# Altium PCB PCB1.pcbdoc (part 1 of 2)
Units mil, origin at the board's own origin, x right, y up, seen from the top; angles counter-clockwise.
Board outline 9373 x 7411 mil, 2 copper layers (Top Layer, Bottom Layer); 228 components, 128 nets, 653 pads, 371 vias.
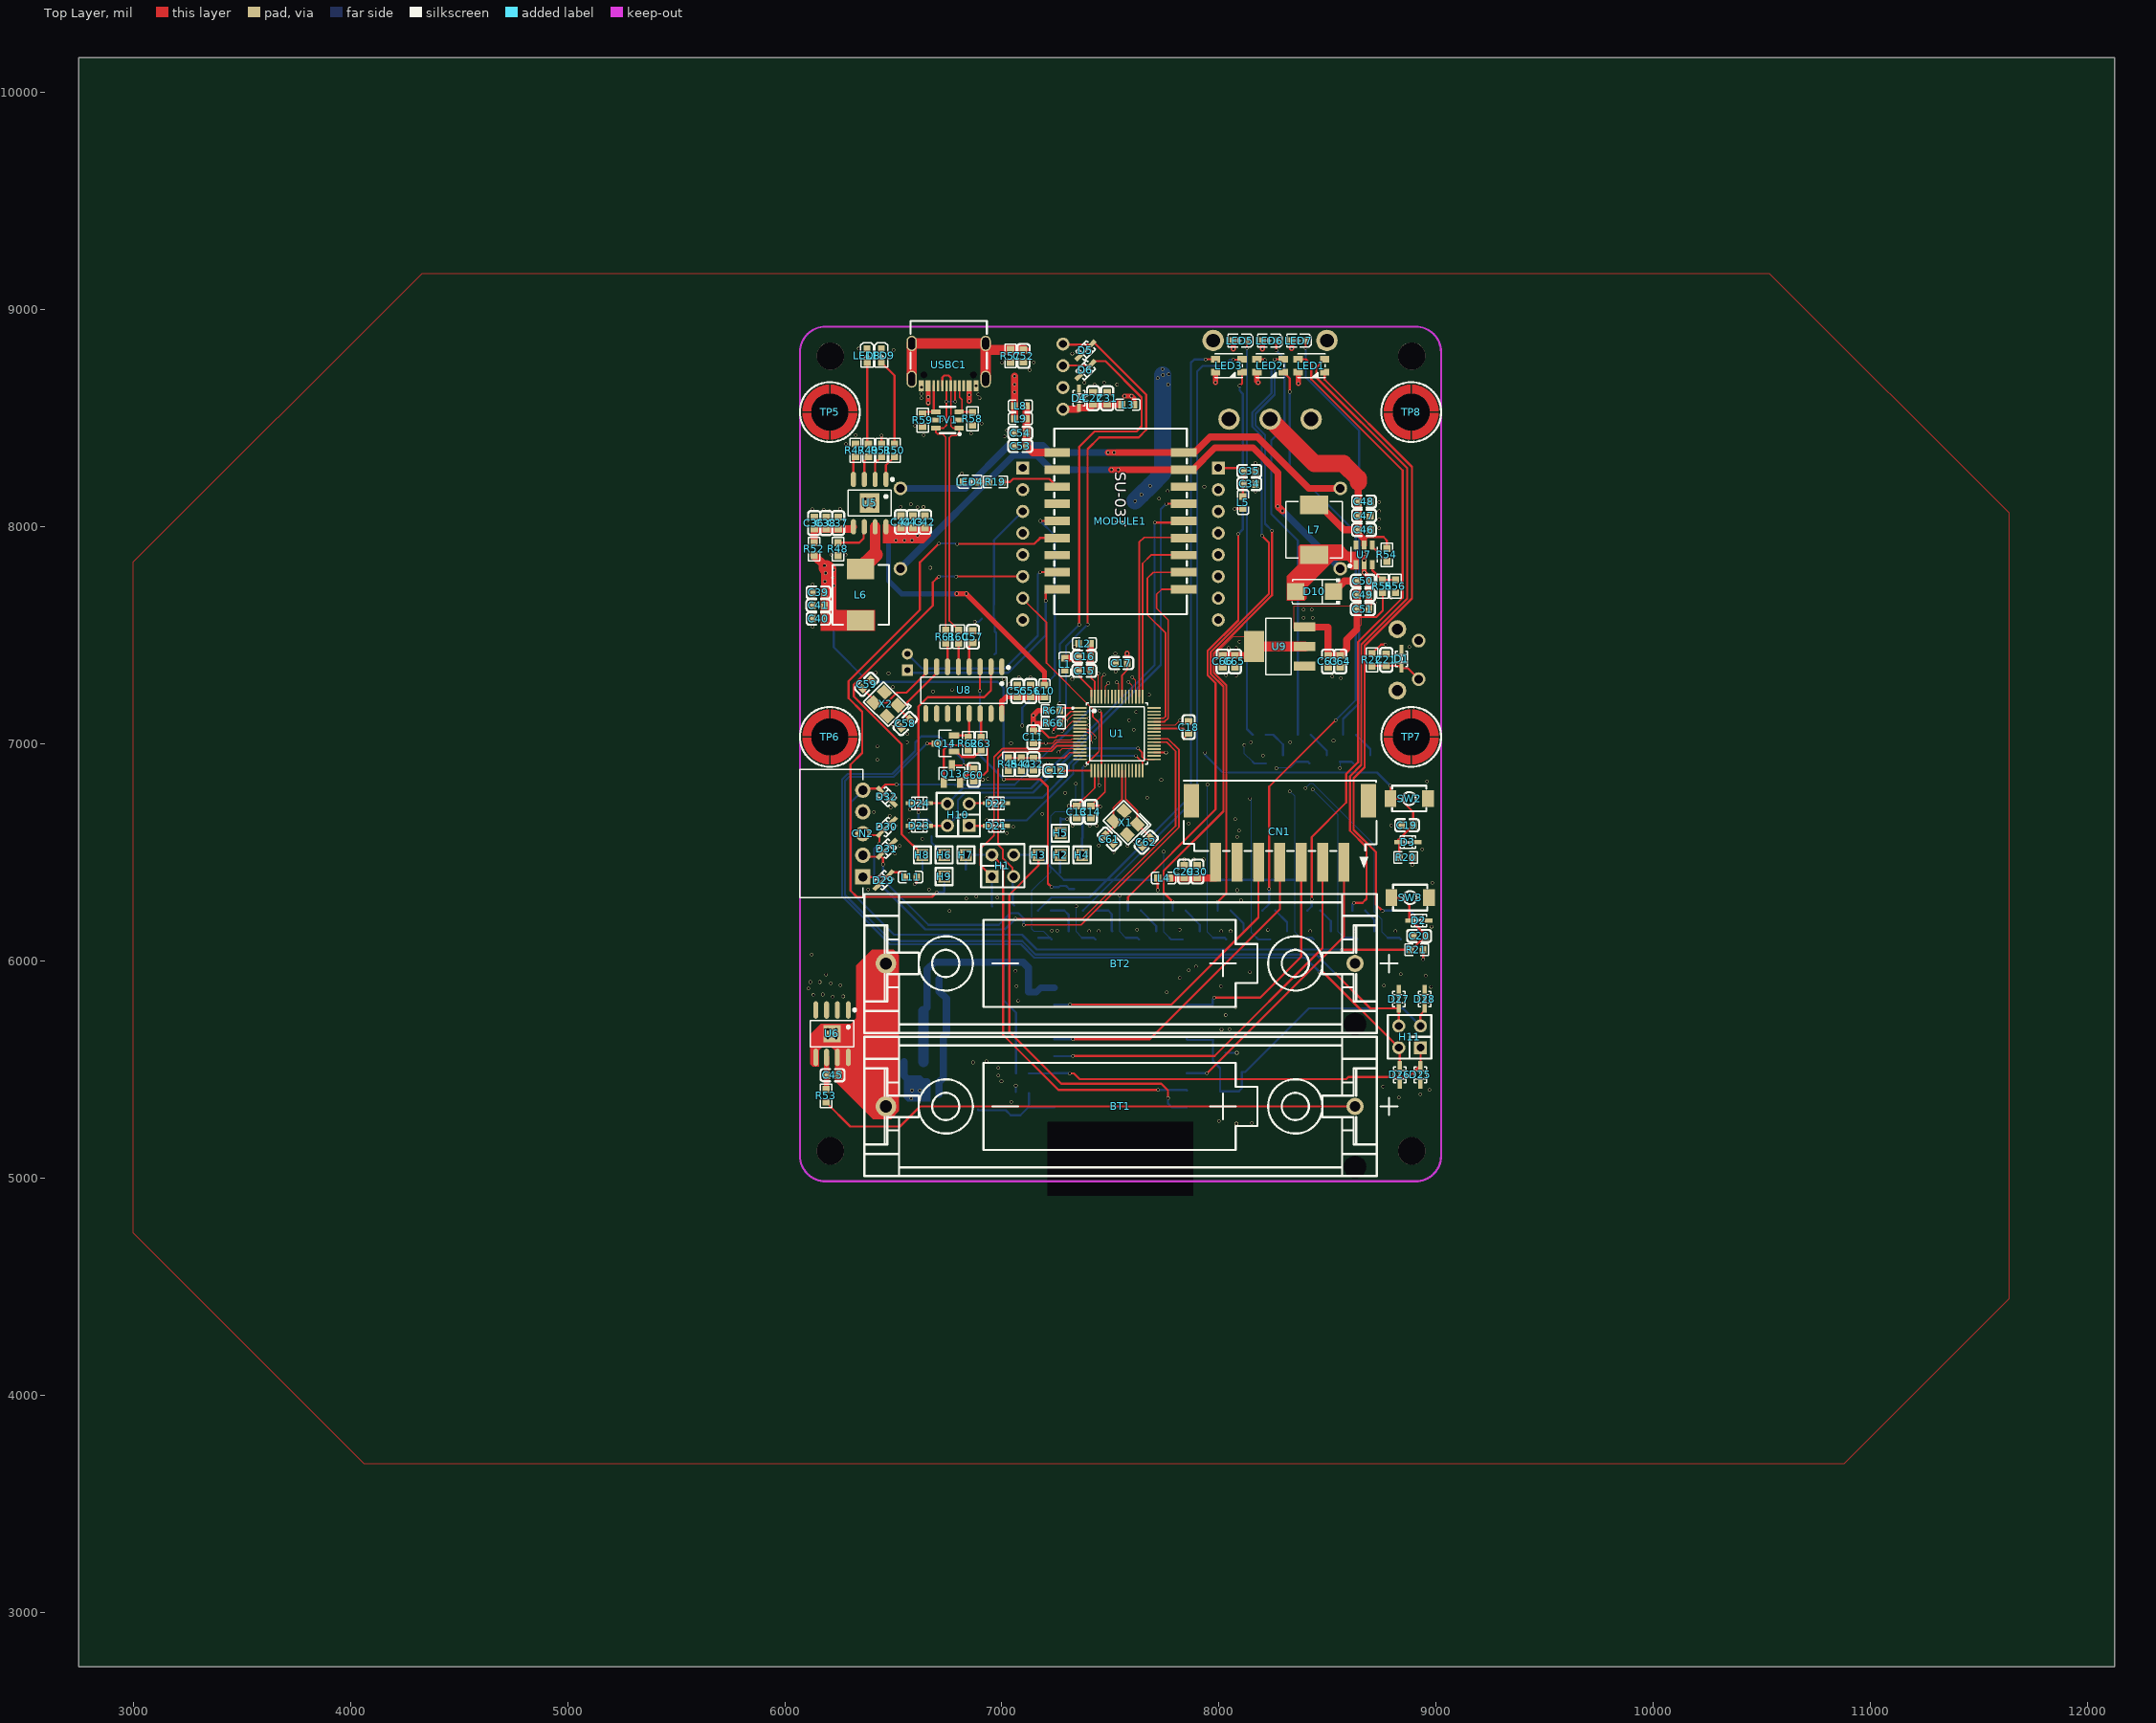
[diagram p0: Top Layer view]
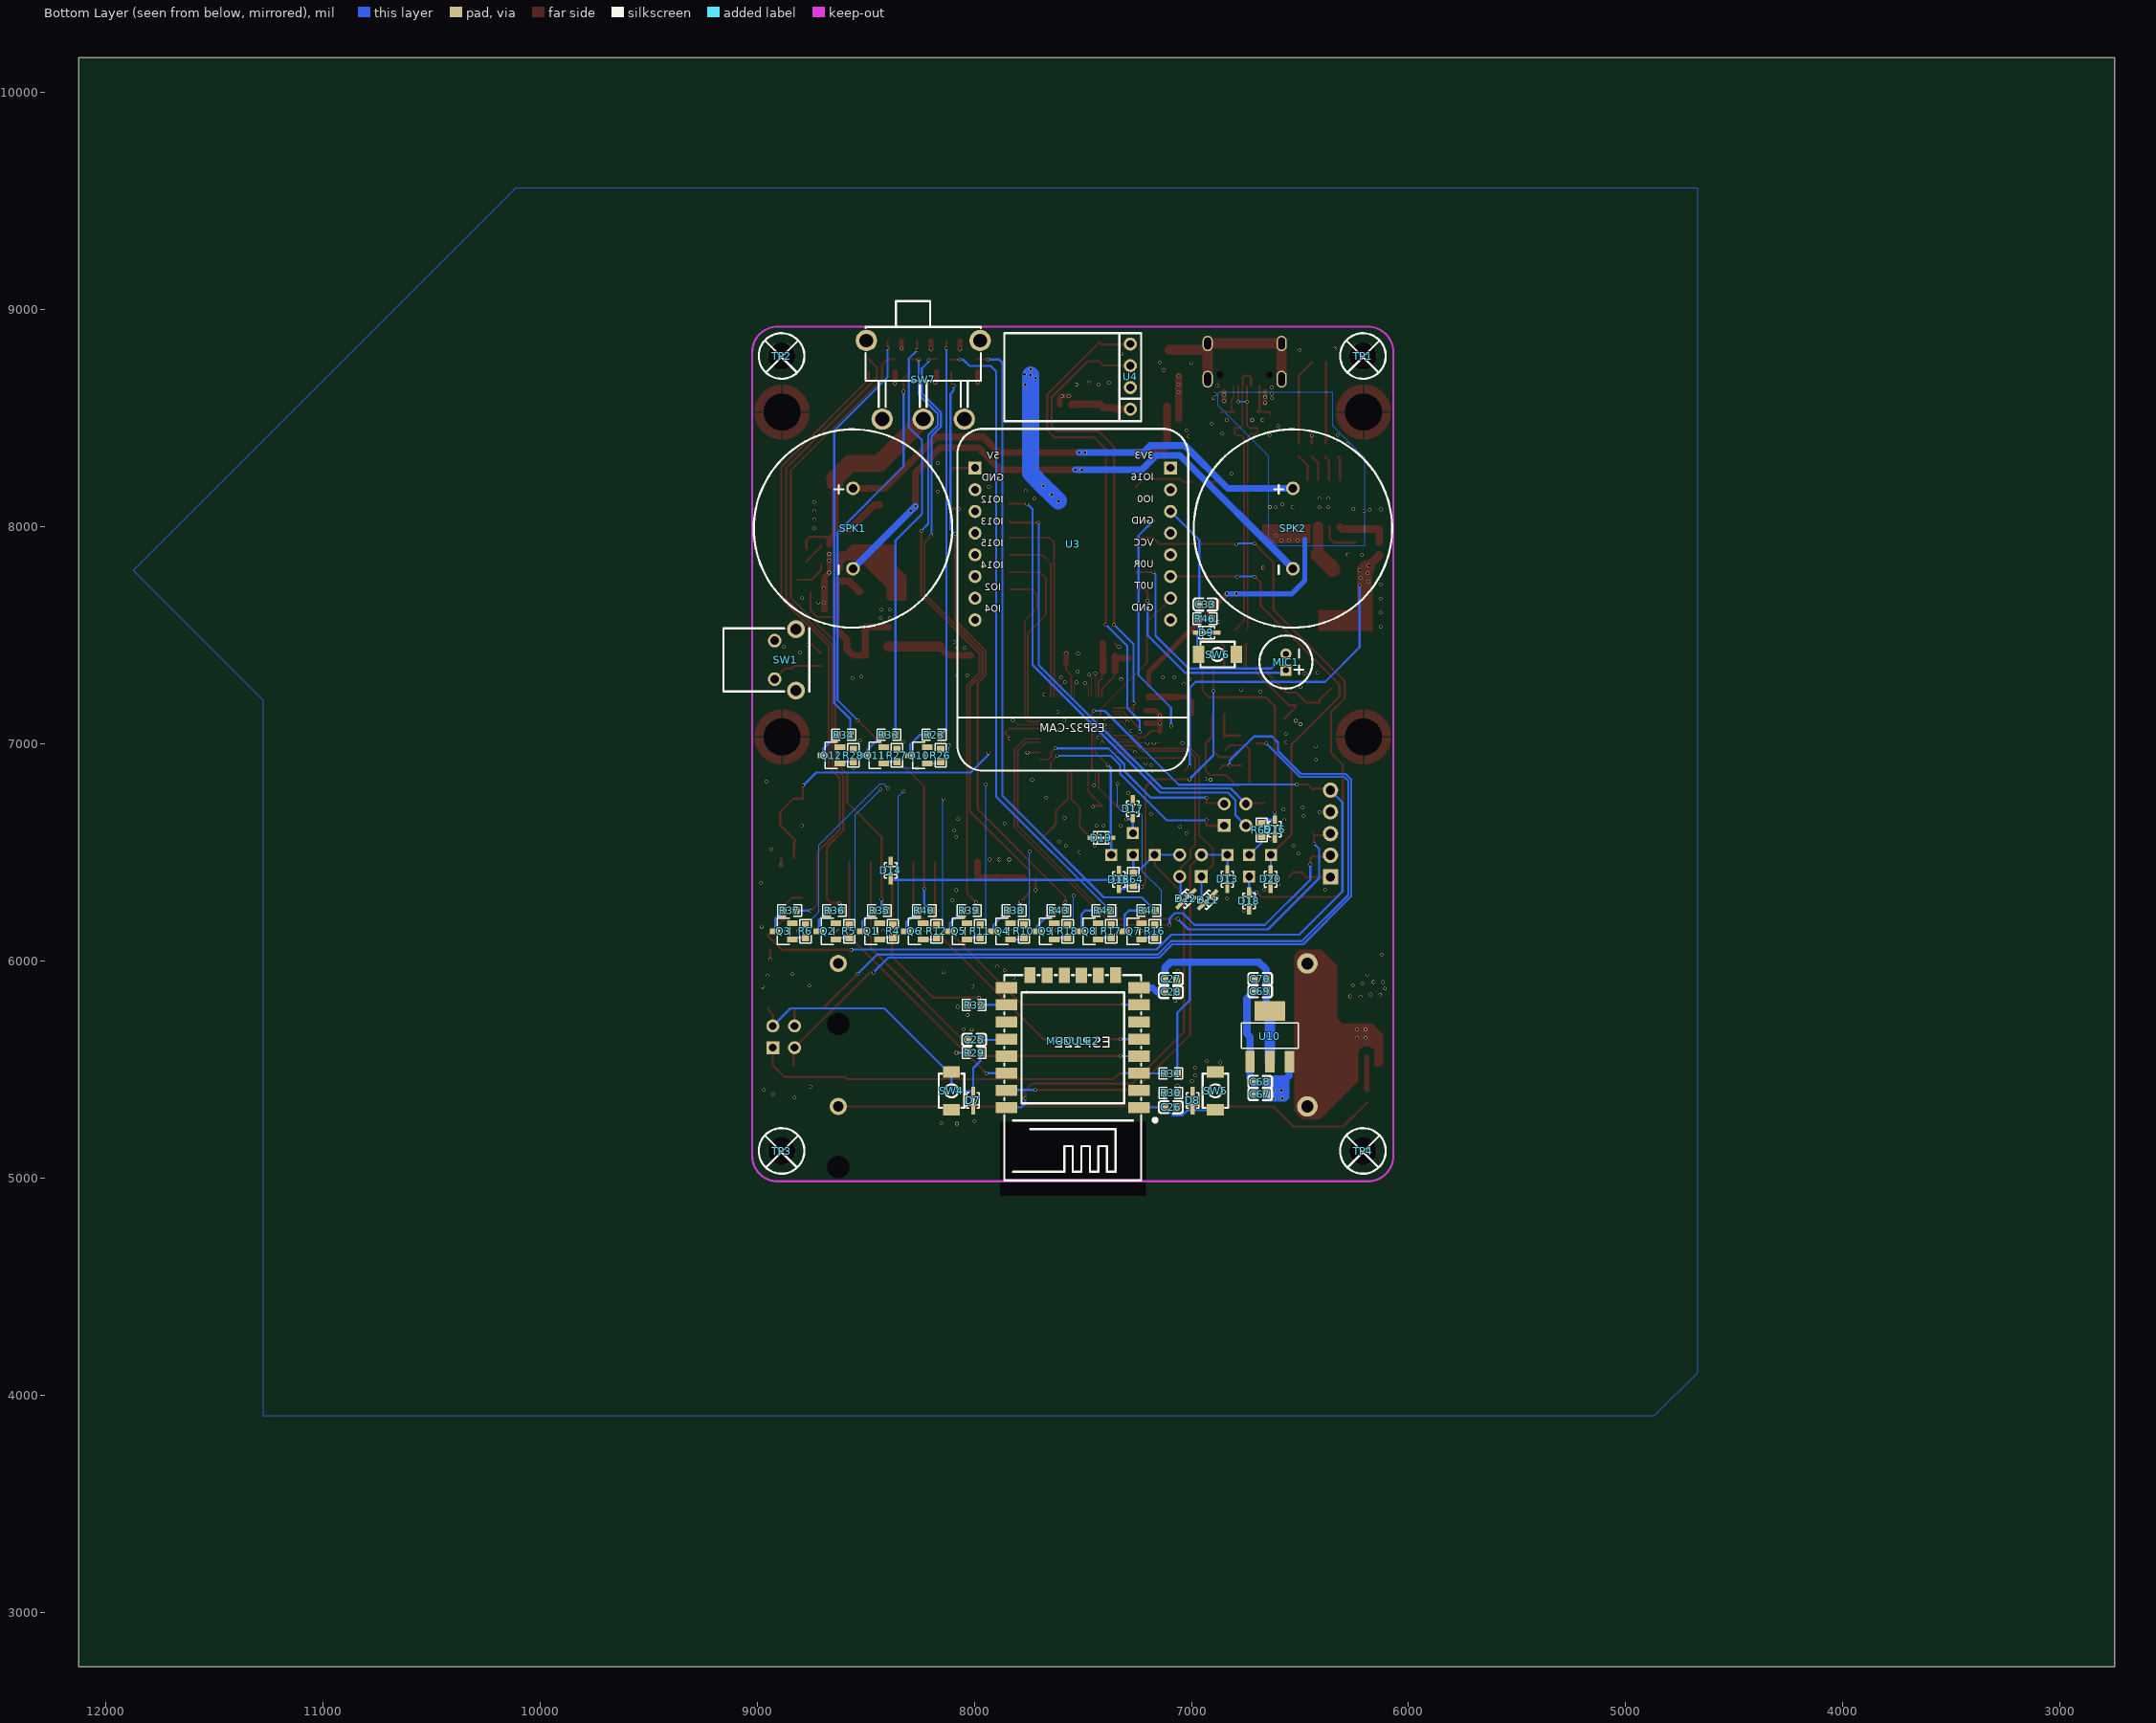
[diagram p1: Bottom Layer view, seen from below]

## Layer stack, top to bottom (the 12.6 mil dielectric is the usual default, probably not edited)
Top Layer: signal copper (thickness not stored)
Dielectric: dielectric 12.6, FR-4, Dk 4.8
Bottom Layer: signal copper (thickness not stored)

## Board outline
12123,2750 2750,2750 2750,10161 12123,10161
cut-out: 7211.73,4920.98 7881.02,4920.98 7881.02,5259.09 7211.73,5259.09

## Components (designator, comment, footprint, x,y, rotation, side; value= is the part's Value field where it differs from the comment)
BT1 "1028" BAT-TH_KEYSTONE-1028 7546.38,5331.3 r180 top
BT2 "1028" BAT-TH_KEYSTONE-1028 7546.38,5989.93 r180 top
C11 "CAP_0603" C0603 7145,7033 r90 top
C12 "CAP_0603" C0603 7245,6878 r180 top
C13 "CAP_0603" C0603 7345,6688 r90 top
C14 "CAP_0603" C0603 7410,6688 r90 top
C15 "CAP_0603" C0603 7379.59,7337.8 r180 top
C16 "CAP_0603" C0603 7380,7403 r180 top
C17 "CAP_0603" C0603 7550,7373 r0 top
C18 "CAP_0603" C0603 7860,7078 r270 top
C19 "CAP_0603" C0603 8866.25,6626.15 r0 top
C20 "CAP_0603" C0603 8922.02,6116.15 r0 top
C21 "CAP_0603" C0603 8770,7388 r270 top
C22 "CAP_0603" C0603 7420,8593 r270 top
C25 "CAP_0603" C0603 8000,5638 r180 bottom
C26 "CAP_0603" C0603 7095,5328 r0 bottom
C27 "CAP_0603" C0603 7095,5918 r0 bottom
C28 "CAP_0603" C0603 7095,5858 r0 bottom
C29 "CAP_0603" C0603 7839.59,6412.8 r270 top
C30 "CAP_0603" C0603 7899.59,6412.8 r270 top
C31 "CAP_0603" C0603 7485,8593 r90 top
C32 "CAP_0603" C0603 7145,6908 r90 top
C33 "CAP_0603" C0603 6935.47,7643 r0 bottom
C34 "CAP_0603" C0603 8140,8198 r0 top
C35 "CAP_0603" C0603 8140,8258 r0 top
C36 "CAP_0603" C0603 6136.03,8018.48 r90 top
C37 "CAP_0603" C0603 6246.03,8018.48 r90 top
C38 "CAP_0603" C0603 6191.03,8018.48 r90 top
C39 "CAP_0603" C0603 6155.69,7698.31 r180 top
C40 "CAP_0603" C0603 6155.69,7578.31 r180 top
C41 "CAP_0603" C0603 6155.49,7638.72 r180 top
C42 "CAP_0603" C0603 6646.03,8023.48 r90 top
C43 "CAP_0603" C0603 6591.03,8023.48 r90 top
C44 "CAP_0603" C0603 6536.03,8023.48 r90 top
C45 "CAP_0603" C0603 6220.46,5475.23 r0 top
C46 "CAP_0603" C0603 8668,7986.89 r0 top
C47 "CAP_0603" C0603 8668,8051.89 r0 top
C48 "CAP_0603" C0603 8668,8116.89 r0 top
C49 "CAP_0603" C0603 8663,7686.89 r0 top
C50 "CAP_0603" C0603 8663,7751.89 r0 top
C51 "CAP_0603" C0603 8663,7621.89 r0 top
C52 "CAP_0603" C0603 7100,8788 r90 top
C53 "CAP_0603" C0603 7085,8373 r0 top
C54 "CAP_0603" C0603 7085,8433 r0 top
C55 "CAP_0603" C0603 7071.46,7244.82 r90 top
C56 "CAP_0603" C0603 7131.46,7244.82 r90 top
C57 "CAP_0603" C0603 6866.46,7494.82 r90 top
C58 "CAP_0603" C0603 6555.63,7094.59 r45 top
C59 "CAP_0603" C0603 6377.6,7275.65 r45 top
C60 "CAP_0603" C0603 6870,6858 r270 top
C61 "CAP_0603" C0603 7495.28,6562.42 r315 top
C62 "CAP_0603" C0603 7665,6548 r45 top
C63 "CAP_0603" C0603 8502,7381.06 r90 top
C64 "CAP_0603" C0603 8558,7381.06 r90 top
C65 "CAP_0603" C0603 8073,7381.06 r90 top
C66 "CAP_0603" C0603 8017,7381.06 r90 top
C67 "CAP_0603" C0603 6683.24,5388.22 r180 bottom
C68 "CAP_0603" C0603 6683.24,5443.85 r180 bottom
C69 "CAP_0603" C0603 6683.24,5861.79 r180 bottom
C70 "CAP_0603" C0603 6683.24,5917.9 r180 bottom
CN1 "X8821WRS-07-9TSN" CONN-SMD_X8821WRS-07-9TSN 8280,6598 r180 top
CN2 "XH-5AW" CONN-TH_5P-P2.54_XH-5AW_C2908614 6360,6588 r90 top
D1 "SD03C_C502532" SOD-323_L1.8-W1.3-LS2.5-BI 8840,7393 r90 top
D2 "SD03C_C502532" SOD-323_L1.8-W1.3-LS2.5-BI 8920,6188 r0 top
D3 "SD03C_C502532" SOD-323_L1.8-W1.3-LS2.5-BI 8870,6548 r0 top
D4 "SD03C_C502532" SOD-323_L1.8-W1.3-LS2.5-BI 7355,8593 r90 top
D5 "SD03C_C502532" SOD-323_L1.8-W1.3-LS2.5-BI 7385,8813 r225 top
D6 "SD03C_C502532" SOD-323_L1.8-W1.3-LS2.5-BI 7385,8723 r225 top
D7 "SD03C_C502532" SOD-323_L1.8-W1.3-LS2.5-BI 8005,5358 r270 bottom
D8 "SD03C_C502532" SOD-323_L1.8-W1.3-LS2.5-BI 6995,5358 r90 bottom
D9 "SD03C_C502532" SOD-323_L1.8-W1.3-LS2.5-BI 6929.81,7513 r180 bottom
D10 "SS34_C8678" SMA_L4.3-W2.6-LS5.2-RD 8440,7703 r180 top
D11 "SD03C_C502532" SOD-323_L1.8-W1.3-LS2.5-BI 6925,6283 r135 bottom
D12 "SD03C_C502532" SOD-323_L1.8-W1.3-LS2.5-BI 7025,6288 r135 bottom
D13 "SD03C_C502532" SOD-323_L1.8-W1.3-LS2.5-BI 6835,6378 r270 bottom
D14 "SD03C_C502532" SOD-323_L1.8-W1.3-LS2.5-BI 8385,6418 r90 bottom
D15 "SD03C_C502532" SOD-323_L1.8-W1.3-LS2.5-BI 7333.38,6376.39 r90 bottom
D16 "SD03C_C502532" SOD-323_L1.8-W1.3-LS2.5-BI 6615,6608 r270 bottom
D17 "SD03C_C502532" SOD-323_L1.8-W1.3-LS2.5-BI 7270,6703 r90 bottom
D18 "SD03C_C502532" SOD-323_L1.8-W1.3-LS2.5-BI 6735,6278 r270 bottom
D19 "SD03C_C502532" SOD-323_L1.8-W1.3-LS2.5-BI 7415,6568 r0 bottom
D20 "SD03C_C502532" SOD-323_L1.8-W1.3-LS2.5-BI 6635,6378 r270 bottom
D21 "SD03C_C502532" SOD-323_L1.8-W1.3-LS2.5-BI 6975,6623 r0 top
D22 "SD03C_C502532" SOD-323_L1.8-W1.3-LS2.5-BI 6975,6728 r0 top
D23 "SD03C_C502532" SOD-323_L1.8-W1.3-LS2.5-BI 6620,6623 r180 top
D24 "SD03C_C502532" SOD-323_L1.8-W1.3-LS2.5-BI 6620,6728 r180 top
D25 "SD03C_C502532" SOD-323_L1.8-W1.3-LS2.5-BI 8927.59,5476.75 r270 top
D26 "SD03C_C502532" SOD-323_L1.8-W1.3-LS2.5-BI 8832.59,5476.75 r270 top
D27 "SD03C_C502532" SOD-323_L1.8-W1.3-LS2.5-BI 8827.59,5826.75 r90 top
D28 "SD03C_C502532" SOD-323_L1.8-W1.3-LS2.5-BI 8947.59,5826.75 r90 top
D29 "SD03C_C502532" SOD-323_L1.8-W1.3-LS2.5-BI 6455,6373 r225 top
D30 "SD03C_C502532" SOD-323_L1.8-W1.3-LS2.5-BI 6470,6618 r45 top
D31 "SD03C_C502532" SOD-323_L1.8-W1.3-LS2.5-BI 6470,6518 r45 top
D32 "SD03C_C502532" SOD-323_L1.8-W1.3-LS2.5-BI 6470,6758 r315 top
H1 "HDR-M_2.54_2x2" HDR-TH_4P-P2.54-V-M-R2-C2-S2.54-1 7004.25,6439.93 r0 top
H2 "HDR-M_2.54_1x1P" HDR-TH_1P-V-M_XKB_X4611WV-01I-C28D40 7269.25,6489.93 r0 top
H3 "HDR-M_2.54_1x1P" HDR-TH_1P-V-M_XKB_X4611WV-01I-C28D40 7169.25,6489.93 r180 top
H4 "HDR-M_2.54_1x1P" HDR-TH_1P-V-M_XKB_X4611WV-01I-C28D40 7369.25,6489.93 r180 top
H5 "HDR-M_2.54_1x1P" HDR-TH_1P-V-M_XKB_X4611WV-01I-C28D40 7269.25,6589.93 r180 top
H6 "HDR-M_2.54_1x1P" HDR-TH_1P-V-M_XKB_X4611WV-01I-C28D40 6734.25,6489.93 r0 top
H7 "HDR-M_2.54_1x1P" HDR-TH_1P-V-M_XKB_X4611WV-01I-C28D40 6834.25,6489.93 r0 top
H8 "HDR-M_2.54_1x1P" HDR-TH_1P-V-M_XKB_X4611WV-01I-C28D40 6634.25,6489.93 r0 top
H9 "HDR-M_2.54_1x1P" HDR-TH_1P-V-M_XKB_X4611WV-01I-C28D40 6734.25,6389.93 r0 top
H10 "HDR-M_2.54_2x2" HDR-TH_4P-P2.54-V-M-R2-C2-S2.54-1 6799.12,6675.13 r90 top
H11 "HDR-M_2.54_2x2" HDR-TH_4P-P2.54-V-M-R2-C2-S2.54-1 8877.59,5651.75 r90 top
L1 "L_0603" L0603 7290,7368 r270 top
L2 "L_0603" L0603 7380,7463 r180 top
L3 "L_0603" L0603 7580,8563 r0 top
L4 "L_0603" L0603 7745,6383 r0 top
L5 "L_0603" L0603 8110,8113 r270 top
L6 "MWSA0603S-2R2MT" IND-SMD_L7.0-W6.6 6350,7688 r270 top
L7 "MWSA0603S-100MT" IND-SMD_L7.1-W6.6 8438,7986.89 r270 top
L8 "L_0603" L0603 7085.63,8557.9 r0 top
L9 "L_0603" L0603 7085.63,8497.9 r0 top
L10 "L_0603" L0603 7196.46,7244.82 r90 top
L11 "L_0603" L0603 6580,6388 r0 top
LED1 "XL-3528RGBW-HM" LED-SMD_4P-L3.2-W2.8-LS3.5-BL-CW 8425,8743 r0 top
LED2 "XL-3528RGBW-HM" LED-SMD_4P-L3.2-W2.8-LS3.5-BL-CW 8235,8743 r0 top
LED3 "XL-3528RGBW-HM" LED-SMD_4P-L3.2-W2.8-LS3.5-BL-CW 8045,8743 r0 top
LED4 "LED_0603-G" LED_0603 6855,8208 r0 top
LED5 "LED_0603-G" LED_0603 8095,8858 r180 top
LED6 "LED_0603-G" LED_0603 8230,8858 r180 top
LED7 "LED_0603-G" LED_0603 8365,8858 r180 top
LED8 "LED_0603-G" LED_0603 6380,8788 r270 top
LED9 "LED_0603-G" LED_0603 6445,8788 r270 top
MIC1 "GMI6050P-60db" MIC-TH_BD6.0-P1.90-D0.4-L-RD 6565,7378 r90 bottom
MODULE1 "SU-03T" COMM-SMD_18P-L21.0-W15.0-P2.00 7546.38,8028 r0 top
MODULE2 "ESP-12E_C89297" WIFIM-SMD_ESP-12E-BR 7546.38,5631.19 r90 bottom
Q1 "2N7002" SOT-23-3_L2.9-W1.3-P1.90-LS2.4-BR 8475.32,6138 r180 bottom
Q2 "2N7002" SOT-23-3_L2.9-W1.3-P1.90-LS2.4-BR 8676.41,6138 r180 bottom
Q3 "2N7002" SOT-23-3_L2.9-W1.3-P1.90-LS2.4-BR 8877.49,6138 r180 bottom
Q4 "2N7002" SOT-23-3_L2.9-W1.3-P1.90-LS2.4-BR 7872.06,6138 r180 bottom
Q5 "2N7002" SOT-23-3_L2.9-W1.3-P1.90-LS2.4-BR 8073.15,6138 r180 bottom
Q6 "2N7002" SOT-23-3_L2.9-W1.3-P1.90-LS2.4-BR 8274.24,6138 r180 bottom
Q7 "2N7002" SOT-23-3_L2.9-W1.3-P1.90-LS2.4-BR 7268.8,6138 r180 bottom
Q8 "2N7002" SOT-23-3_L2.9-W1.3-P1.90-LS2.4-BR 7469.89,6138 r180 bottom
Q9 "2N7002" SOT-23-3_L2.9-W1.3-P1.90-LS2.4-BR 7670.98,6138 r180 bottom
Q10 "2N7002" SOT-23-3_L2.9-W1.3-P1.90-LS2.4-BR 8255.54,6948 r180 bottom
Q11 "2N7002" SOT-23-3_L2.9-W1.3-P1.90-LS2.4-BR 8456.63,6948 r180 bottom
Q12 "2N7002" SOT-23-3_L2.9-W1.3-P1.90-LS2.4-BR 8657.72,6948 r180 bottom
Q13 "SS8050_C2150" SOT-23-3_L2.9-W1.3-P1.90-LS2.4-BR 6770,6863 r270 top
Q14 "SS8050_C2150" SOT-23-3_L2.9-W1.3-P1.90-LS2.4-BR 6740,7003 r0 top
R4 "10k" R0603 8374.78,6138 r270 bottom
R5 "10k" R0603 8575.86,6138 r270 bottom
R6 "10k" R0603 8776.95,6138 r270 bottom
R10 "10k" R0603 7771.52,6138 r270 bottom
R11 "10k" R0603 7972.61,6138 r270 bottom
R12 "10k" R0603 8173.69,6138 r270 bottom
R16 "10k" R0603 7168.26,6138 r270 bottom
R17 "10k" R0603 7369.35,6138 r270 bottom
R18 "10k" R0603 7570.43,6138 r270 bottom
R19 "Res_0603" R0603 6970,8208 r0 top
R20 "10k" R0603 8860,6478 r0 top
R21 "10k" R0603 8910,6053 r0 top
R22 "10k" R0603 8705,7388 r90 top
R23 "470" R0603 8185,7043 r180 bottom
R26 "10k" R0603 8155,6948 r270 bottom
R27 "10k" R0603 8356.09,6948 r270 bottom
R28 "10k" R0603 8557.17,6948 r270 bottom
R29 "10k" R0603 8000,5578 r0 bottom
R30 "10k" R0603 7095,5393 r180 bottom
R31 "10k" R0603 7095,5483 r180 bottom
R32 "22k" R0603 8000,5798 r180 bottom
R33 "470" R0603 8393.18,7043 r180 bottom
R34 "470" R0603 8601.36,7043 r180 bottom
R35 "470" R0603 8436.69,6233 r180 bottom
R36 "470" R0603 8643.34,6233 r180 bottom
R37 "470" R0603 8850,6233 r180 bottom
R38 "470" R0603 7816.72,6233 r180 bottom
R39 "470" R0603 8023.38,6233 r180 bottom
R40 "470" R0603 8230.03,6233 r180 bottom
R41 "470" R0603 7196.76,6233 r180 bottom
R42 "470" R0603 7403.41,6233 r180 bottom
R43 "470" R0603 7610.07,6233 r180 bottom
R44 "10k" R0603 7090,6908 r90 top
R45 "10k" R0603 7030,6908 r270 top
R46 "10k" R0603 6937.69,7578 r180 bottom
R47 "Res_0603" R0603 6326.03,8353.48 r90 top
R48 "Res_0603" R0603 6246.03,7898.48 r270 top
R49 "Res_0603" R0603 6386.03,8353.48 r270 top
R50 "Res_0603" R0603 6506.03,8353.48 r270 top
R51 "Res_0603" R0603 6446.03,8353.48 r270 top
R52 "Res_0603" R0603 6136.03,7898.48 r90 top
R53 "Res_0603" R0603 6190.46,5380.23 r270 top
R54 "Res_0603" R0603 8773,7871.89 r270 top
R55 "Res_0603" R0603 8753,7726.89 r270 top
R56 "Res_0603" R0603 8813,7726.89 r90 top
R57 "10k" R0603 7040,8788 r90 top
R58 "Res_0603" R0603 6865,8498 r90 top
R59 "Res_0603" R0603 6635,8492 r90 top
R60 "Res_0603" R0603 6801.46,7494.82 r270 top
R61 "Res_0603" R0603 6741.46,7494.82 r270 top
R62 "Res_0603" R0603 6845,7003 r90 top
R63 "Res_0603" R0603 6905,7003 r90 top
R64 "Res_0603" R0603 7268.48,6376.35 r90 bottom
R65 "Res_0603" R0603 6676.51,6604.63 r270 bottom
R66 "Res_0603" R0603 7237,7097 r180 top
R67 "Res_0603" R0603 7237,7155 r180 top
SPK1 "FS-2308" BEEP-TH_BD23.2-P9.20-D1.0 8558.6,7993.12 r90 bottom
SPK2 "FS-2308" BEEP-TH_BD23.2-P9.20-D1.0 6532.69,7993.12 r90 bottom
SW1 "KAN0637-0701B" SW-TH_KAN0637-0701B 8870,7388 r270 bottom
SW2 "YTSA010A0252501B" SW-SMD_L4.0-W3.0-LS5.0 8875.59,6749.25 r0 top
SW3 "YTSA010A0252501B" SW-SMD_L4.0-W3.0-LS5.0 8880,6293 r0 top
SW4 "YTSA010A0252501B" SW-SMD_L4.0-W3.0-LS5.0 8105,5403 r270 bottom
SW5 "YTSA010A0252501B" SW-SMD_L4.0-W3.0-LS5.0 6890,5403 r90 bottom
SW6 "YTSA010A0252501B" SW-SMD_L4.0-W3.0-LS5.0 6880,7413 r180 bottom
SW7 "SS-12D11L3" SW-TH_SS-12D11L3 8235,8678 r180 bottom
TP1 "M3螺丝" M3螺丝 6207.8,8785.2 r180 bottom
TP2 "M3螺丝" M3螺丝 8884.96,8785.2 r180 bottom
TP3 "M3螺丝" M3螺丝 8884.96,5123.79 r180 bottom
TP4 "M3螺丝" M3螺丝 6207.8,5123.79 r180 bottom
TP5 "SMTSO3040MTJ" SMD_BD5.6-D4.1 6207.8,8529.3 r0 top
TP6 "SMTSO3040MTJ" SMD_BD5.6-D4.1 6207.8,7033.24 r0 top
TP7 "SMTSO3040MTJ" SMD_BD5.6-D4.1 8884.96,7033.24 r0 top
TP8 "SMTSO3040MTJ" SMD_BD5.6-D4.1 8884.96,8529.3 r0 top
TV1 "SRV05-4-P-T7_C85364" SOT-23-6_L2.9-W1.6-P0.95-LS2.8-BR 6750,8493 r0 top
U1 "HT32F52352" LQFP-64_L7.0-W7.0-P0.40-LS9.2-BL 7530,7048 r270 top
U3 "ESP32CAM" ESP32CAM 7546.38,7664.87 r0 bottom
U4 "GY906" GY906 7546.38,8690.2 r270 bottom
U5 "IP2312U_VSET" sop-8_l4.9-w3.9-p1.27-ls6.0-bl-ep 6391.46,8110.06 r180 top
U6 "XB8886A" soic-8_l5.0-w4.0-p1.27-ls6.0-bl-ep2.0 6217.82,5666.36 r180 top
U7 "MT3608" SOT-23-6_L2.9-W1.6-P0.95-LS2.8-BL 8668,7871.89 r0 top
U8 "CH340G" SOIC-16_L9.9-W3.9-P1.27-LS6.0-BL 6824.87,7248.31 r180 top
U9 "AMS1117-3.3_C6186" SOT-223-3_L6.5-W3.4-P2.30-LS7.0-BR 8277.48,7449.68 r0 top
U10 "AMS1117-3.3_C6186" SOT-223-3_L6.5-W3.4-P2.30-LS7.0-BR 6639.63,5653.81 r270 bottom
USBC1 "TYPE-C-31-M-12" USB-C_SMD-TYPE-C-31-M-12 6755,8748 r180 top
X1 "X32258MSB4SI" CRYSTAL-SMD_4P-L3.2-W2.5-BL 7570,6638 r135 top
X2 "X322512MSB4SI" OSC-SMD_4P-L3.2-W2.5-BL 6465.63,7184.59 r135 top

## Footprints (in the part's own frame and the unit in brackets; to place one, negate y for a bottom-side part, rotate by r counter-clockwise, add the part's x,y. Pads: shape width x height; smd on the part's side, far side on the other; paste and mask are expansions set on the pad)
BAT-TH_KEYSTONE-1028 [mm]
  round 2 hole 1.2 paste+0 mask+0.051: 1(-27.43,0)
  round 2.4 hole 1.4 paste+0 mask+0.051: 2(27.43,0)
  Multi-Layer board cut-out: -28.73,7.09 -28.601,6.526 -28.241,6.074 -27.719,5.822 -27.141,5.822 -26.619,6.074 -26.259,6.526 -26.13,7.09 -26.13,7.09 -26.259,7.654 -26.619,8.106 -27.141,8.357 -27.719,8.357 -28.241,8.106 -28.601,7.654 -28.73,7.09
  silkscreen extent -32.42,-8.13 29.97,8.13
BEEP-TH_BD23.2-P9.20-D1.0 [mm]
  round 1.6 hole 1 paste+0 mask+0.051: 1(4.7,0) 2(-4.7,0)
  silkscreen extent -11.6,-11.6 11.6,11.6
C0603 [mm]
  rect 0.8x0.9 smd paste+0 mask+0.051: 1(-0.7,0) 2(0.7,0)
  silkscreen extent -1.41,-0.71 1.39,0.72
COMM-SMD_18P-L21.0-W15.0-P2.00 [mm]
  rect 3x1 smd paste+0 mask+0.051: 1(-7.4,8) 2(-7.4,6) 3(-7.4,4) 4(-7.4,2) 5(-7.4,0) 6(-7.4,-2) 7(-7.4,-4) 8(-7.4,-6) 9(-7.4,-8) 10(7.4,-8) 11(7.4,-6) 12(7.4,-4) 13(7.4,-2) 14(7.4,0) 15(7.4,2) 16(7.4,4) 17(7.4,6) 18(7.4,8)
  silkscreen extent -7.75,-10.92 7.75,10.79
CONN-SMD_X8821WRS-07-9TSN [mm]
  rect 1.3x4.5 smd paste+0 mask+0.051: 1(-7.5,3.6) 2(-5,3.6) 3(-2.5,3.6) 4(0,3.6) 5(2.5,3.6) 6(5,3.6) 7(7.5,3.6)
  rect 1.8x3.9 smd paste+0 mask+0.051: 8(10.34,-3.6) 9(-10.34,-3.6)
  silkscreen extent -11.3,-5.92 11.25,4.3
CONN-TH_5P-P2.54_XH-5AW_C2908614 [mm]
  rect 1.8x1.8 hole 1.1 paste+0 mask+0.05: 1(-5.08,0)
  round 1.8 hole 1.1 paste+0 mask+0.05: 2(-2.54,0) 3(0,0) 4(2.54,0) 5(5.08,0)
  silkscreen extent -7.5,0 7.5,7.4
CRYSTAL-SMD_4P-L3.2-W2.5-BL [mm]
  rect 1.4x1.2 smd paste+0 mask+0.051: 1(-1.1,-0.85) 2(1.1,-0.85) 3(1.1,0.85) 4(-1.1,0.85)
  silkscreen extent -2.26,-1.91 2.03,1.68
ESP32CAM [mil]
  round 60 hole 36 paste+4 mask+4: 1(450,92.9) 2(450,-7.1) 3(450,-107.1) 4(450,-207.1) 5(450,-307.1) 6(450,-407.1) 7(450,-507.1) 10(-450,-507.1) 11(-450,-407.1) 12(-450,-307.1) 13(-450,-207.1) 14(-450,-107.1) 15(-450,-7.1) 16(-450,92.9)
  rect 60x60 hole 36 paste+4 mask+4: 8(450,-607.1) 9(-450,-607.1)
  silkscreen extent -531,-787 532,787
GY906 [mil]
  round 60 hole 36 paste+0 mask+2: 1(147.5,264.96) 2(47.5,264.96) 3(-52.5,264.96) 4(-152.5,264.96)
  silkscreen extent -203,-315 203,315
HDR-TH_1P-V-M_XKB_X4611WV-01I-C28D40 [mm]
  rect 1.4x1.4 hole 0.9 paste+0 mask+0.051: 1(0,0)
  silkscreen extent -1,-1 1,1
HDR-TH_4P-P2.54-V-M-R2-C2-S2.54-1 [mil]
  rect 60x60 hole 36 paste+0 mask+2: 1(-50,-50)
  round 60 hole 36 paste+0 mask+2: 2(-50,50) 3(50,-50) 4(50,50)
  silkscreen extent -100,-100 100,100
IND-SMD_L7.0-W6.6 [mm]
  rect 2.4x3.2 smd paste+0 mask+0.051: 1(-3,0) 2(3,0)
  silkscreen extent -3.5,-3.3 3.5,3.3
IND-SMD_L7.1-W6.6 [mm]
  rect 2.15x3.32 smd paste+0 mask+0.051: 1(-2.913,0) 2(2.913,0)
  silkscreen extent -3.3,-3.3 3.3,3.3
L0603 [mm]
  rect 0.8x0.864 smd paste-100 mask+0.051: 1(-0.7,0) 2(0.7,0)
  silkscreen extent -1.42,-0.65 1.41,0.67
LED-SMD_4P-L3.2-W2.8-LS3.5-BL-CW [mil]
  rect 43.3x31.5 smd paste+0 mask+1.97: 1(-61,-29.5) 2(-61,29.5) 3(61,29.5) 4(61,-29.5)
  silkscreen extent -63,-55 63,55
LED_0603 [mil]
  rect 31.5x31.5 smd paste+0 mask+2: 1(-33.5,-0.4) 2(29.5,-0.2)
  silkscreen extent -61,-30 53,30
LQFP-64_L7.0-W7.0-P0.40-LS9.2-BL [mm]
  rect 0.2x1.6 smd paste+0 mask+0.051: 1(-3,-4.33) 2(-2.6,-4.33) 3(-2.2,-4.33) 4(-1.8,-4.33) 5(-1.4,-4.33) 6(-1,-4.33) 7(-0.6,-4.33) 8(-0.2,-4.33) 9(0.2,-4.33) 10(0.6,-4.33) 11(1,-4.33) 12(1.4,-4.33) 13(1.8,-4.33) 14(2.2,-4.33) 15(2.6,-4.33) 16(3,-4.33) 33(3,4.33) 34(2.6,4.33) 35(2.2,4.33) 36(1.8,4.33) 37(1.4,4.33) 38(1,4.33) 39(0.6,4.33) 40(0.2,4.33) 41(-0.2,4.33) 42(-0.6,4.33) 43(-1,4.33) 44(-1.4,4.33) 45(-1.8,4.33) 46(-2.2,4.33) 47(-2.6,4.33) 48(-3,4.33)
  rect 1.6x0.2 smd paste+0 mask+0.051: 17(4.33,-3) 18(4.33,-2.6) 19(4.33,-2.2) 20(4.33,-1.8) 21(4.33,-1.4) 22(4.33,-1) 23(4.33,-0.6) 24(4.33,-0.2) 25(4.33,0.2) 26(4.33,0.6) 27(4.33,1) 28(4.33,1.4) 29(4.33,1.8) 30(4.33,2.2) 31(4.33,2.6) 32(4.33,3) 49(-4.33,3) 50(-4.33,2.6) 51(-4.33,2.2) 52(-4.33,1.8) 53(-4.33,1.4) 54(-4.33,1) 55(-4.33,0.6) 56(-4.33,0.2) 57(-4.33,-0.2) 58(-4.33,-0.6) 59(-4.33,-1) 60(-4.33,-1.4) 61(-4.33,-1.8) 62(-4.33,-2.2) 63(-4.33,-2.6) 64(-4.33,-3)
  silkscreen extent -3.58,-5.26 3.58,3.58
M3螺丝 [mil]
  round 126 hole 126 paste+0 mask+4: 1(-2.5,2.5)
  silkscreen extent -108,-102 102,107
MIC-TH_BD6.0-P1.90-D0.4-L-RD [mm]
  rect 1.3x1.3 hole 0.7 paste+0 mask+0.051: 1(-0.95,0)
  round 1.3 hole 0.7 paste+0 mask+0.051: 2(0.95,0)
  silkscreen extent -3.1,-3.1 3.1,3.1
OSC-SMD_4P-L3.2-W2.5-BL [mm]
  rect 1.4x1.2 smd paste+0 mask+0.051: 1(-1.1,-0.875) 2(1.1,-0.875) 3(1.1,0.875) 4(-1.1,0.875)
  silkscreen extent -2.29,-1.9 2.03,1.65
R0603 [mil]
  rect 31.8x34 smd paste-3937.01 mask+2: 1(-29.7,0) 2(29.7,0)
  silkscreen extent -55,-26 55,26
SMA_L4.3-W2.6-LS5.2-RD [mm]
  rect 2x2 smd paste+0 mask+0.051: 1(-2.2,0) 2(2.2,0)
  silkscreen extent -2.98,-1.5 2.6,1.5
SMD_BD5.6-D4.1 [mil]
  Top Layer region: 125.98,3.94 86.61,3.94 86.45,6.61 86.21,9.27 85.89,11.92 85.48,14.57 84.99,17.19 84.43,19.81 83.78,22.4 83.05,24.97 82.24,27.52 81.35,30.05 80.39,32.54 79.35,35 78.23,37.43 77.04,39.83 75.78,42.18 74.45,44.5 73.04,46.77 71.56,49 70.02,51.19 68.41,53.32 66.73,55.4 64.99,57.44 63.19,59.41 61.33,61.33 59.41,63.19 57.44,64.99 55.4,66.73 53.32,68.41 51.19,70.02 49,71.56 46.77,73.04 44.5,74.44 42.18,75.78 39.83,77.04 37.43,78.23 35,79.35 32.54,80.39 30.05,81.35 27.52,82.24 24.97,83.05 22.4,83.78 19.81,84.43 17.2,84.99 14.57,85.48 11.92,85.89 9.27,86.21 6.61,86.45 3.94,86.61 3.94,125.98 7.16,125.84 10.37,125.62 13.58,125.32 16.78,124.93 19.97,124.46 23.14,123.91 26.3,123.28 29.45,122.57 32.57,121.78 35.67,120.91 38.75,119.95 41.81,118.93 44.83,117.82 47.83,116.64 50.8,115.38 53.73,114.04 56.63,112.63 59.49,111.15 62.31,109.59 65.09,107.96 67.83,106.26 70.52,104.5 73.17,102.66 75.77,100.76 78.32,98.79 80.82,96.75 83.27,94.66 85.66,92.5 88,90.28 90.28,88 92.5,85.66 94.66,83.27 96.75,80.82 98.79,78.32 100.76,75.77 102.66,73.17 104.5,70.52 106.26,67.83 107.96,65.09 109.59,62.31 111.15,59.49 112.63,56.63 114.04,53.73 115.38,50.8 116.64,47.83 117.82,44.83 118.93,41.81 119.95,38.75 120.91,35.67 121.78,32.57 122.57,29.45 123.28,26.3 123.91,23.14 124.46,19.97 124.93,16.78 125.32,13.58 125.62,10.37 125.84,7.16
  Top Layer region: -3.94,125.98 -3.94,86.61 -6.61,86.45 -9.27,86.21 -11.92,85.89 -14.57,85.48 -17.19,84.99 -19.81,84.43 -22.4,83.78 -24.97,83.05 -27.52,82.24 -30.05,81.35 -32.54,80.39 -35,79.35 -37.43,78.23 -39.83,77.04 -42.18,75.78 -44.5,74.44 -46.77,73.04 -49,71.56 -51.19,70.02 -53.32,68.41 -55.4,66.73 -57.43,64.99 -59.41,63.19 -61.33,61.33 -63.19,59.41 -64.99,57.44 -66.73,55.4 -68.41,53.32 -70.02,51.19 -71.56,49 -73.04,46.77 -74.44,44.5 -75.78,42.18 -77.04,39.83 -78.23,37.43 -79.35,35 -80.39,32.54 -81.35,30.05 -82.24,27.52 -83.05,24.97 -83.78,22.4 -84.43,19.81 -84.99,17.19 -85.48,14.57 -85.89,11.92 -86.21,9.27 -86.45,6.61 -86.61,3.94 -125.98,3.94 -125.84,7.16 -125.62,10.37 -125.32,13.58 -124.93,16.78 -124.46,19.97 -123.91,23.14 -123.28,26.3 -122.57,29.45 -121.78,32.57 -120.9,35.67 -119.95,38.75 -118.93,41.81 -117.82,44.83 -116.64,47.83 -115.38,50.8 -114.04,53.73 -112.63,56.63 -111.15,59.49 -109.59,62.31 -107.96,65.09 -106.26,67.83 -104.5,70.52 -102.66,73.17 -100.76,75.77 -98.79,78.32 -96.75,80.82 -94.65,83.27 -92.5,85.66 -90.28,88 -88,90.28 -85.66,92.5 -83.27,94.66 -80.82,96.75 -78.32,98.79 -75.77,100.76 -73.17,102.66 -70.52,104.5 -67.83,106.26 -65.09,107.96 -62.31,109.59 -59.49,111.15 -56.63,112.63 -53.73,114.04 -50.8,115.38 -47.83,116.64 -44.83,117.82 -41.81,118.93 -38.75,119.95 -35.67,120.91 -32.57,121.78 -29.45,122.57 -26.3,123.28 -23.14,123.91 -19.97,124.46 -16.78,124.93 -13.58,125.32 -10.37,125.62 -7.16,125.84
  Top Layer region: -125.98,-3.94 -86.61,-3.94 -86.45,-6.61 -86.21,-9.27 -85.89,-11.92 -85.48,-14.57 -84.99,-17.19 -84.43,-19.81 -83.78,-22.4 -83.05,-24.97 -82.24,-27.52 -81.35,-30.05 -80.39,-32.54 -79.35,-35 -78.23,-37.43 -77.04,-39.83 -75.78,-42.18 -74.44,-44.5 -73.04,-46.77 -71.56,-49 -70.02,-51.19 -68.41,-53.32 -66.73,-55.4 -64.99,-57.43 -63.19,-59.41 -61.33,-61.33 -59.41,-63.19 -57.43,-64.99 -55.4,-66.73 -53.32,-68.41 -51.19,-70.02 -49,-71.56 -46.77,-73.04 -44.5,-74.44 -42.18,-75.78 -39.83,-77.04 -37.43,-78.23 -35,-79.35 -32.54,-80.39 -30.05,-81.35 -27.52,-82.24 -24.97,-83.05 -22.4,-83.78 -19.81,-84.42 -17.19,-84.99 -14.57,-85.48 -11.92,-85.89 -9.27,-86.21 -6.61,-86.45 -3.94,-86.61 -3.94,-125.98 -7.16,-125.84 -10.37,-125.62 -13.58,-125.32 -16.78,-124.93 -19.97,-124.46 -23.14,-123.91 -26.3,-123.28 -29.45,-122.57 -32.57,-121.78 -35.67,-120.9 -38.75,-119.95 -41.81,-118.93 -44.83,-117.82 -47.83,-116.64 -50.8,-115.38 -53.73,-114.04 -56.63,-112.63 -59.49,-111.15 -62.31,-109.59 -65.09,-107.96 -67.83,-106.26 -70.52,-104.5 -73.17,-102.66 -75.77,-100.76 -78.32,-98.79 -80.82,-96.75 -83.27,-94.65 -85.66,-92.5 -88,-90.28 -90.28,-88 -92.5,-85.66 -94.65,-83.27 -96.75,-80.82 -98.79,-78.32 -100.76,-75.77 -102.66,-73.17 -104.5,-70.52 -106.26,-67.83 -107.96,-65.09 -109.59,-62.31 -111.15,-59.49 -112.63,-56.63 -114.04,-53.73 -115.38,-50.8 -116.64,-47.83 -117.82,-44.83 -118.93,-41.81 -119.95,-38.75 -120.9,-35.67 -121.78,-32.57 -122.57,-29.45 -123.28,-26.3 -123.91,-23.14 -124.46,-19.97 -124.93,-16.78 -125.32,-13.58 -125.62,-10.37 -125.84,-7.16
  Top Layer region: 3.94,-125.98 3.94,-86.61 6.61,-86.45 9.27,-86.21 11.92,-85.89 14.57,-85.48 17.2,-84.99 19.81,-84.42 22.4,-83.78 24.97,-83.05 27.52,-82.24 30.05,-81.35 32.54,-80.39 35,-79.35 37.43,-78.23 39.83,-77.04 42.18,-75.78 44.5,-74.44 46.77,-73.04 49,-71.56 51.19,-70.02 53.32,-68.41 55.4,-66.73 57.44,-64.99 59.41,-63.19 61.33,-61.33 63.19,-59.41 64.99,-57.43 66.73,-55.4 68.41,-53.32 70.02,-51.19 71.56,-49 73.04,-46.77 74.45,-44.5 75.78,-42.18 77.04,-39.83 78.23,-37.43 79.35,-35 80.39,-32.54 81.35,-30.05 82.24,-27.52 83.05,-24.97 83.78,-22.4 84.43,-19.81 84.99,-17.19 85.48,-14.57 85.89,-11.92 86.21,-9.27 86.45,-6.61 86.61,-3.94 125.98,-3.94 125.84,-7.16 125.62,-10.37 125.32,-13.58 124.93,-16.78 124.46,-19.97 123.91,-23.14 123.28,-26.3 122.57,-29.45 121.78,-32.57 120.91,-35.67 119.95,-38.75 118.93,-41.81 117.82,-44.83 116.64,-47.83 115.38,-50.8 114.04,-53.73 112.63,-56.63 111.15,-59.49 109.59,-62.31 107.96,-65.09 106.26,-67.83 104.5,-70.52 102.66,-73.17 100.76,-75.77 98.79,-78.32 96.75,-80.82 94.66,-83.27 92.5,-85.66 90.28,-88 88,-90.28 85.66,-92.5 83.27,-94.65 80.82,-96.75 78.32,-98.79 75.77,-100.76 73.17,-102.66 70.52,-104.5 67.83,-106.26 65.09,-107.96 62.31,-109.59 59.49,-111.15 56.63,-112.63 53.73,-114.04 50.8,-115.38 47.83,-116.64 44.83,-117.82 41.81,-118.93 38.75,-119.95 35.67,-120.9 32.57,-121.78 29.45,-122.57 26.3,-123.28 23.14,-123.91 19.97,-124.46 16.78,-124.93 13.58,-125.32 10.37,-125.62 7.16,-125.84
  Multi-Layer board cut-out: 84.65,0 76.26,36.73 52.78,66.18 18.84,82.52 -18.84,82.52 -52.78,66.18 -76.26,36.73 -84.65,0 -84.65,0 -76.26,-36.73 -52.78,-66.18 -18.84,-82.52 18.84,-82.52 52.78,-66.18 76.26,-36.73 84.65,0
  silkscreen extent -138,-138 138,138
SOD-323_L1.8-W1.3-LS2.5-BI [mm]
  rect 0.985x0.49 smd paste+0 mask+0.051: 1(-1.118,0) 2(1.118,0)
  silkscreen extent -0.9,-0.73 0.9,0.73
soic-8_l5.0-w4.0-p1.27-ls6.0-bl-ep2.0 [mm]
  oval 0.574x2.038 smd paste+0 mask+0.051: 1(-1.905,-2.769) 2(-0.635,-2.769) 3(0.635,-2.769) 4(1.905,-2.769) 5(1.905,2.769) 6(0.635,2.769) 7(-0.635,2.769) 8(-1.905,2.769)
  rect 2x2 smd paste+0 mask+0.051: 9(0,0)
  silkscreen extent -2.79,-2.92 2.53,1.52
SOIC-16_L9.9-W3.9-P1.27-LS6.0-BL [mil]
  oval 23.7x77.6 smd paste+0 mask+2: 1(-175,-107.7) 2(-125,-107.7) 3(-75,-107.7) 4(-25,-107.7) 5(25,-107.7) 6(75,-107.7) 7(125,-107.7) 8(175,-107.7) 9(175,107.7) 10(125,107.7) 11(75,107.7) 12(25,107.7) 13(-25,107.7) 14(-75,107.7) 15(-125,107.7) 16(-175,107.7)
  silkscreen extent -211,-111 198,60
sop-8_l4.9-w3.9-p1.27-ls6.0-bl-ep [mm]
  oval 0.6x1.8 smd paste+0 mask+0.051: 1(-1.905,-2.772) 2(-0.635,-2.772) 3(0.635,-2.772) 4(1.905,-2.772) 5(1.905,2.772) 6(0.635,2.772) 7(-0.635,2.772) 8(-1.905,2.772)
  rect 2.29x2.29 smd paste+0 mask+0.051: 9(0,0)
  silkscreen extent -2.8,-2.92 2.53,1.52
SOT-23-3_L2.9-W1.3-P1.90-LS2.4-BR [mil]
  rect 49.2x27.6 smd paste+0 mask+2: 1(39.4,-37.4) 2(39.4,37.4) 3(-39.4,0)
  silkscreen extent -29,-60 29,60
SOT-23-6_L2.9-W1.6-P0.95-LS2.8-BL [mil]
  rect 20.95x42.2 smd paste+0 mask+2: 1(-37.4,-45.24) 2(0,-45.24) 3(37.4,-45.24) 4(37.4,45.24) 5(0,45.24) 6(-37.4,45.24)
  silkscreen extent -72,-57 61,35
SOT-23-6_L2.9-W1.6-P0.95-LS2.8-BR [mm]
  rect 1.1x0.6 smd paste+0 mask+0.051: 1(1.35,-0.95) 2(1.35,0) 3(1.35,0.95) 4(-1.35,0.95) 5(-1.35,0) 6(-1.35,-0.95)
  silkscreen extent -0.9,-1.78 1.52,1.55
SOT-223-3_L6.5-W3.4-P2.30-LS7.0-BR [mm]
  rect 2.5x1.1 smd paste+0 mask+0.051: 1(2.97,-2.3) 2(2.97,0) 3(2.97,2.3)
  rect 2.34x3.6 smd paste+0 mask+0.051: 4(-2.97,0)
  silkscreen extent -1.57,-3.33 1.37,3.33
SW-SMD_L4.0-W3.0-LS5.0 [mm]
  rect 1.35x2 smd paste+0 mask+0.051: 1(-2.2,0) 2(2.2,0)
  silkscreen extent -2,-1.5 2,1.5
SW-TH_KAN0637-0701B [mm]
  round 1.6 hole 1 paste+0 mask+0.051: 1(-2.25,-1.25) 2(2.25,-1.25)
  round 2.1 hole 1.3 paste+0 mask+0.051: 3(-3.6,1.25) 4(3.6,1.25)
  silkscreen extent -3.7,-7.25 3.7,2.8
SW-TH_SS-12D11L3 [mm]
  round 2.5 hole 1.7 paste+0 mask+0.051: 1(-4.8,-4.6) 2(0,-4.6) 3(4.8,-4.6)
  round 2.5 hole 1.6 paste+0 mask+0.051: 4(-6.65,4.6) 5(6.65,4.6)
  silkscreen extent -6.75,-3.17 6.75,9.21
USB-C_SMD-TYPE-C-31-M-12 [mm]
  oval 1.2x2 hole 0.8 slot 1.6 at 90 deg paste+0 mask+0.051: 0(-4.325,1.706) 1(4.325,1.706)
  oval 1.2x1.8 hole 0.8 slot 1.4 at 90 deg paste+0 mask+0.051: 2(4.325,-2.474) 3(-4.325,-2.474)
  rect 0.3x1.3 smd paste-100 mask+0.051: A1(-3.35,2.474) A4(-2.55,2.474) A5(-1.25,2.474) A6(-0.25,2.474) A7(0.25,2.474) A8(1.25,2.474) A9(2.55,2.474) A12(3.35,2.474) B1(3.05,2.474) B4(2.25,2.474) B5(1.75,2.474) B6(0.75,2.474) B7(-0.75,2.474) B8(-1.75,2.474) B9(-2.25,2.474) B12(-3.05,2.474)
  Multi-Layer board cut-out: -3.275,1.206 -3.238,1.043 -3.134,0.912 -2.983,0.84 -2.816,0.84 -2.666,0.912 -2.562,1.043 -2.525,1.206 -2.525,1.206 -2.562,1.368 -2.666,1.499 -2.816,1.571 -2.983,1.571 -3.134,1.499 -3.238,1.368 -3.275,1.206
  Multi-Layer board cut-out: 2.525,1.206 2.562,1.043 2.666,0.912 2.816,0.84 2.983,0.84 3.134,0.912 3.238,1.043 3.275,1.206 3.275,1.206 3.238,1.368 3.134,1.499 2.983,1.571 2.816,1.571 2.666,1.499 2.562,1.368 2.525,1.206
  silkscreen extent -4.47,-5.09 4.47,0.49
WIFIM-SMD_ESP-12E-BR [mm]
  rect 1.3x2.5 smd paste-100 mask+0.051: 1(-7.74,-7.75) 2(-5.74,-7.75) 3(-3.74,-7.75) 4(-1.74,-7.75) 5(0.26,-7.75) 6(2.26,-7.75) 7(4.26,-7.75) 8(6.26,-7.75) 15(6.26,7.75) 16(4.26,7.75) 17(2.26,7.75) 18(0.26,7.75) 19(-1.74,7.75) 20(-3.74,7.75) 21(-5.74,7.75) 22(-7.74,7.75)
  rect 1.8x1.3 smd paste-100 mask+0.051: 9(7.74,-5.001) 10(7.739,-3.001) 11(7.739,-1.001) 12(7.739,0.999) 13(7.739,2.999) 14(7.74,4.999)
  silkscreen extent -16.26,-9.82 7.74,8

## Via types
v1: diameter 15.75, hole 11.81, Top Layer to Bottom Layer, 371 vias

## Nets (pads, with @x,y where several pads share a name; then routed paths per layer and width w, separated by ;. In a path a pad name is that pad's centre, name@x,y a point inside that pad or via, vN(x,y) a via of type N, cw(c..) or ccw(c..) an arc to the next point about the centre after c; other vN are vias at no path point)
$1N1274: Q1.3 R35.1 | length 115
  Bottom Layer w10: R35.1@8466.39,6233 8514.72,6184.67 Q1.3@8514.72,6138
$1N1275: Q2.3 R36.1 | length 112.7
  Bottom Layer w10: R36.1@8673.04,6233 8715.81,6190.24 Q2.3@8715.81,6138
$1N1276: Q3.3 R37.1 | length 110.4
  Bottom Layer w10: R37.1@8879.7,6233 8916.89,6195.81 Q3.3@8916.89,6138
$1N1277: LED1.2 R35.2 | length 2941
  Top Layer w10: LED1.2@8364,8772.5 8399.5,8772.5 8425,8747 8425,8681 8845,8261 8845,7674 8640,7469 8640,6916 8586,6862 8586,6731 8427,6572 v1(8427,6285)
  Bottom Layer w10: R35.2@8406.99,6233 8427,6253.01 v1(8427,6285)
$1N1278: LED1.4 R37.2 | length 2882.4
  Top Layer w10: LED1.4@8486,8713.5 8486,8679.5 8888,8277.5 8888,7670.94 8670,7452.94 8670,6893 8620,6843 8620,6605 8722,6503 8722,6262 v1(8752,6232)
  Bottom Layer w10: v1(8752,6232) 8753,6233 R37.2@8820.3,6233
$1N1285: LED1.3 R36.2 | length 2918.7
  Top Layer w10: LED1.3@8486,8772.5 8448,8734.5 8448,8689 8866,8271 8866,7670 8654.98,7458.98 8654.98,6904 8603,6852.02 8603,6601 8679,6525 8679,6288 8660,6269 v1(8621,6269)
  Bottom Layer w10: R36.2@8613.64,6233 8613.64,6261.64 v1(8621,6269)
$1N1774: Q4.3 R38.1 | length 121.9
  Bottom Layer w10: R38.1@7846.42,6233 7911.46,6167.96 Q4.3@7911.46,6138
$1N1775: Q5.3 R39.1 | length 119.6
  Bottom Layer w10: R39.1@8053.08,6233 8112.55,6173.53 Q5.3@8112.55,6138
$1N1776: Q6.3 R40.1 | length 117.3
  Bottom Layer w10: R40.1@8259.73,6233 8313.64,6179.1 Q6.3@8313.64,6138
$1N1777: LED2.2 R38.2 | length 2922.1
  Top Layer w10: v1(7787.02,6274) 7745,6316.02 7745,6416 8019.98,6690.98 8019.98,7265.19 7961.98,7323.19 7961.98,7423.81 8229.98,7691.81 8229.98,7928.02 v1(8198,7960) ; LED2.2@8174,8772.5 8208.5,8772.5 v1(8211,8770)
  Bottom Layer w10: R38.2@7787.02,6233 v1(7787.02,6274) ; v1(8198,7960) 8197,7961 8197,8419.18 8153.98,8462.19 8153.98,8527.81 8241.98,8615.81 8241.98,8730 8211,8760.98 v1(8211,8770)
$1N1780: LED2.4 R40.2 | length 2796.8
  Top Layer w10: v1(8231,6332) 8231,6804 v1(8537,7110) ; LED2.4@8296,8713.5 8325,8684.5 v1(8325,8623)
  Bottom Layer w10: R40.2@8200.33,6233 8231,6263.67 v1(8231,6332) ; v1(8325,8623) 8325,8280 8630,7975 8630,7203 v1(8537,7110)
$1N1790: LED2.3 R39.2 | length 2798.4
  Top Layer w10: v1(7993,6272) 8034,6313 8034,7271 7976,7329 7976,7418 8244,7686 v1(8244,7983) ; v1(8256,8772.5) LED2.3@8296,8772.5
  Bottom Layer w10: R39.2@7993.68,6233 v1@7993.68,6271 ; v1(8244,7983) 8212,8015 8212,8424 8168,8468 8168,8522 8256,8610 v1(8256,8772.5)
$1N2254: Q7.3 R41.1 | length 164.6
  Bottom Layer w10: R41.1@7226.46,6233 7287.46,6233 7308.2,6212.26 Q7.3@7308.2,6138
$1N2255: Q8.3 R42.1 | length 159.9
  Bottom Layer w10: R42.1@7433.11,6233 7490,6233 7506,6217 7506,6141.29 Q8.3@7509.29,6138
$1N2256: Q9.3 R43.1 | length 124.2
  Bottom Layer w10: R43.1@7639.77,6233 7710.38,6162.39 Q9.3@7710.38,6138
$1N2257: LED3.2 R41.2 | length 3037.5
  Top Layer w10: v1(7938,8772) 7938.5,8772.5 LED3.2@7984,8772.5
  Bottom Layer w10: R41.2@7167.06,6233 7228.06,6294 7403,6294 7871,6762 7871,8757 7886,8772 v1(7938,8772)
$1N2260: LED3.4 R43.2 | length 2739.9
  Top Layer w10: v1(7580.37,6273) 7580.37,6295.37 7984,6699 7984,7281.36 7947.97,7317.39 7947.97,7429.61 8088.18,7569.82 v1(8088.18,7967.82) v1@8088,7968 ; v1(8095,8651) 8106,8662 LED3.4@8106,8713.5
  Bottom Layer w10: R43.2@7580.37,6233 v1(7580.37,6273) ; v1(8088.18,7967.82) 8109,7988.64 8109,8614 8095,8628 v1(8095,8651)
$1N2270: LED3.3 R42.2 | length 2937.4
  Top Layer w10: v1(8066.2,8771) 8104.5,8771 LED3.3@8106,8772.5
  Bottom Layer w10: R42.2@7373.71,6233 7899,6758.29 7899,8717 7924,8742 8022,8742 8051,8771 v1@8072,8771
$1N4341: C15.1 C16.1 L2.1 U1.63 | length 253.2
  Top Layer w7.9: C15.1@7407.15,7337.8 7411,7333.95 7411,7305 7427.64,7288.36 U1.63@7427.64,7218.47
  Top Layer w32: C15.1@7407.15,7337.8 7407.15,7402.59 C16.1@7407.56,7403 L2.1@7407.56,7463
$1N4344: C15.2 C16.2 L1.1 U1.64 | length 274.4
  Top Layer w7.9: C15.2@7352.03,7337.8 7356,7333.83 7356,7311 7411.89,7255.11 U1.64@7411.89,7218.47
  Top Layer w32: L1.1@7290,7395.56 7344.99,7395.56 C16.2@7352.03,7402.59 ; C15.2@7352.03,7337.8 C16.2@7352.03,7402.59 ; C16.2@7352.44,7403 C16.2@7352.03,7402.59
$1N12299: Q10.3 R23.1 | length 148.7
  Bottom Layer w10: R23.1@8214.7,7043 8249.7,7043 8294.94,6997.76 Q10.3@8294.94,6948
$1N12300: Q11.3 R33.1 | length 125.3
  Bottom Layer w10: R33.1@8422.88,7043 8496.03,6969.85 Q11.3@8496.03,6948
$1N12301: Q12.3 R34.1 | length 122.4
  Bottom Layer w10: R34.1@8631.06,7043 8697.12,6976.95 Q12.3@8697.12,6948
$1N12381: LED5.1 R23.2 | length 1826.5
  Top Layer w10: v1(8128.5,8825) LED5.1@8128.5,8858.4
  Bottom Layer w10: v1(8128.5,8825) 8128.5,7069.8 R23.2@8155.3,7043
$1N12383: LED6.1 R33.2 | length 1906.9
  Top Layer w10: v1(8263,8814) 8263.5,8814.5 LED6.1@8263.5,8858.4
  Bottom Layer w10: v1(8263,8814) 8301,8776 8301,8459 8241,8399 8241,8060 8363.48,7937.52 R33.2@8363.48,7043
$1N12385: LED7.1 R34.2 | length 1947.9
  Top Layer w10: LED7.1@8398.5,8858.4 8399,8857.9 v1(8399,8825)
  Bottom Layer w10: v1(8399,8825) 8399,8690 8645.01,8443.99 8645.01,7189.01 8571.66,7115.66 R34.2@8571.66,7043
$1N14843: C22.2 C31.1 D4.1 L3.1 U4.1 | length 281.5
  Top Layer w34: U4.1@7281.42,8542.7 7348.7,8542.7 D4.1@7355,8549 7403.56,8549 C22.2@7420,8565.44 C31.1@7485,8565.44 7550.01,8565.44 L3.1@7552.44,8563
$1N18630: CN2.1 D29.1 L11.1 | length 210.7
  Top Layer w10: CN2.1@6360,6388 6470,6388 D29.1@6486.11,6404.11 6492,6410 6530.44,6410 L11.1@6552.44,6388
$1N20660: C62.2 U1.27 X1.1 | length 357.7
  Top Layer w7.9: U1.27@7569.37,6877.53 7569.37,6746.63 7624.29,6691.71 X1.1@7624.29,6631.04
  Top Layer w10: X1.1@7624.29,6631.04 7684.49,6570.84 C62.2@7684.49,6567.49
$1N20677: C61.1 U1.26 X1.3 | length 330.1
  Top Layer w7.9: X1.3@7515.71,6644.96 7513,6647.67 7513,6706 7553.62,6746.62 U1.26@7553.62,6877.53
  Top Layer w10: C61.1@7475.79,6581.91 7515.71,6621.82 X1.3@7515.71,6644.96
$2N1016: C29.2 C30.2 CN1.7 L4.2 | length 287.3
  Top Layer w32: L4.2@7772.56,6383 7897.35,6383 C30.2@7899.59,6385.24 7901.83,6383 7984.73,6383 CN1.7@7984.73,6456.27
$3N445: C34.1 C35.1 L5.1 U3.8 | length 240.3
  Top Layer w10: U3.8@7996.38,8271.97 8098.47,8271.97 C35.1@8112.44,8258 C34.1@8112.44,8198 8110,8195.56 L5.1@8110,8140.56
$4N378: R47.1 U5.4 | length 108.6
  Top Layer w10: U5.4@6316.46,8219.21 6316.46,8314.25 R47.1@6326.03,8323.78
$4N382: R49.2 U5.3 | length 112.7
  Top Layer w10: U5.3@6366.46,8219.21 6366.46,8304.25 R49.2@6386.03,8323.78
$4N409: R50.2 U5.1 | length 121
  Top Layer w10: U5.1@6466.46,8219.21 6466.46,8284.25 R50.2@6506.03,8323.78
$4N436: R51.2 U5.2 | length 116.9
  Top Layer w10: U5.2@6416.46,8219.21 6416.46,8294.25 R51.2@6446.03,8323.78
$4N459: LED8.2 R49.1 | length 377.9
  Top Layer w10: LED8.2@6379.8,8758.5 6379.8,8389.36 R49.1@6386.03,8383.14
$4N482: LED9.2 R50.1 | length 400.7
  Top Layer w10: LED9.2@6444.8,8758.5 6506.03,8697.27 R50.1@6506.03,8383.14
$4N551: R48.1 U5.6 | length 180.1
  Top Layer w10: R48.1@6246.03,7928.14 6344.14,7928.14 6364,7948 6364,7998.45 U5.6@6366.46,8000.91
$4N629: L6.1 U5.7 | length 222.3
  Top Layer w50: 6416.46,7872.57 U5.7@6416.46,8000.91
  Top Layer w70: L6.1@6350,7806.11 6416.46,7872.57
$4N787: C36.1 C37.1 C38.1 R52.2 U5.5 | length 247.4
  Top Layer w32: R52.2@6136.03,7928.14 C36.1@6136.03,7990.92
  Top Layer w34: C36.1@6136.03,7990.92 C38.1@6191.03,7990.92 C37.1@6246.03,7990.92 6306.47,7990.92 U5.5@6316.46,8000.91
$4N1373: C45.1 R53.1 U6.6 | length 148.5
  Top Layer w24: R53.1@6190.46,5409.93 6192.9,5412.33 C45.1@6192.9,5475.23 6192.82,5475.3 U6.6@6192.82,5557.34
$4N1642: R54.2 U7.4 | length 102.9
  Top Layer w10: U7.4@8705.4,7917.13 8705.4,7909.83 R54.2@8773,7842.19
$4N1934: C46.1 C47.1 C48.1 L7.1 R54.1 SW7.2 U7.5 | length 1246.2
  Top Layer w10: 8668,7943.14 8674.14,7943.14 8685,7954 8757,7954 8773,7938 R54.1@8773,7901.55
  Top Layer w28: 8624.25,7986.89 8668,7943.14 U7.5@8668,7917.13
  Top Layer w32: L7.1@8438,8101.57 8461,8101.57 8575.68,7986.89 8624.25,7986.89 C46.1@8640.44,7986.89 C47.1@8640.44,8051.89 C48.1@8640.44,8116.89 8641,8117.45 8641,8207
  Top Layer w80: SW7.2@8235,8496.9 8439.9,8292 8572,8292 8641,8223 8641,8207
$4N2026: D10.2 L7.2 U7.1
$4N2263: R55.1 R56.2 U7.3 | length 151.9
  Top Layer w10: U7.3@8705.4,7826.65 8705.4,7800.65 8749.5,7756.55 8753,7756.55 R56.2@8813,7756.55
$5N265: MIC1.2 MODULE1.8 | length 1067.7
  Top Layer w10: v1(7175,7792) 7254.81,7792 MODULE1.8@7255.04,7791.77
  Bottom Layer w10: MIC1.2@6565,7415.4 6632.4,7348 7014,7348 7165,7499 7165,7782 v1(7175,7792)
